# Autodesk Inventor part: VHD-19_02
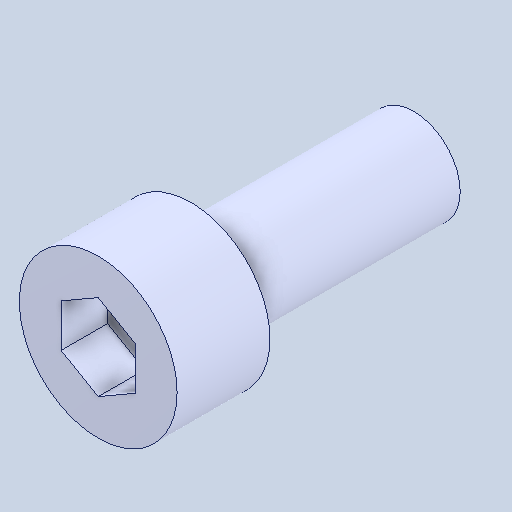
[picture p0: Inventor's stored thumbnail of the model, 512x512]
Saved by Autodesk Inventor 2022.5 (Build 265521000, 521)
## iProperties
Created: 2024-05
Part Number: VHD-19_02
Material: 一般
Document SubType Name: Modeling
Designer: ImaoCorp
Density: 1 g/cm^3
Appearance: 既定
Author: ImaoCorp
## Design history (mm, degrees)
feature "VHD-19_02"
node "ソリッド1"
